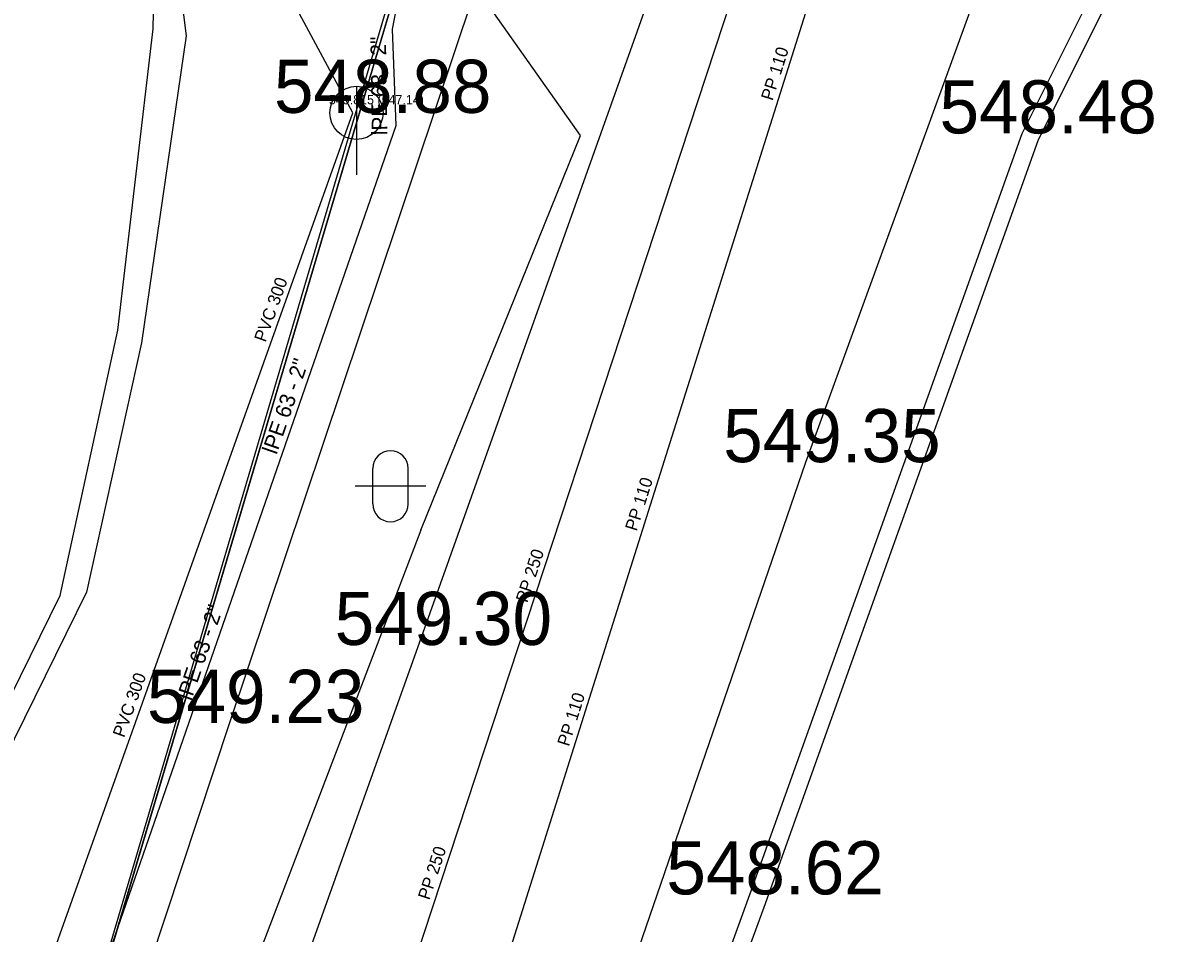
# Model space of a CAD drawing. Extents: x -669995 to -669686, y -1125551 to -1125263.
# Drawn here: x -669845.3 to -669829.31, y -1125387.03 to -1125374.18 of the extents above; entities that cross this region are included whole.
import ezdxf

# ---------------------------------------------------------------- set-up
doc = ezdxf.new("R2010")
doc.units = 0
for name, color, linetype in [('G_Bod_tecka', 7, 'Continuous'), ('G_Bod_vyska', 7, 'Continuous'), ('G_Plochy_zpevnene', 7, 'Continuous'), ('G_Ploty', 7, 'Continuous'), ('G_Site-kanalizace', 7, 'Continuous'), ('G_Z_ELsilove_nadz_kotovane', 7, 'Continuous'), ('G_Z_ELsilove_podz_kotovane', 7, 'Continuous'), ('G_Z_ELsilove_zrusene', 7, 'Continuous'), ('G_Z_KANAL_podz_kotovane', 7, 'Continuous'), ('G_Z_KANAL_podz_priblizne', 7, 'Continuous'), ('G_Z_PLYNY_podz_geodeticky', 7, 'Continuous'), ('G_Z_VODA_podz_kotovane', 7, 'Continuous'), ('G_Zelen-Znacky', 7, 'Continuous'), ('Vrstva 11', 7, 'Continuous'), ('Vrstva 17', 7, 'Continuous'), ('Vrstva 2', 7, 'Continuous'), ('Vrstva 21', 7, 'Continuous'), ('Vrstva 26', 7, 'Continuous'), ('Vrstva 3', 7, 'Continuous'), ('Vrstva 4', 7, 'Continuous'), ('Vrstva 5', 7, 'Continuous'), ('Vrstva 8', 7, 'Continuous')]:
    doc.layers.add(name, color=color, linetype=linetype)

msp = doc.modelspace()

# ---------------------------------------------------------------- linework, layer by layer
at = {"layer": 'G_Bod_tecka'}
for p, q in [((-669840.59, -1125375.45), (-669840.59, -1125375.45)), ((-669831.2, -1125375.74), (-669831.2, -1125375.74)), ((-669834.25, -1125380.38), (-669834.25, -1125380.38)), ((-669839.71, -1125382.96), (-669839.71, -1125382.96)), ((-669842.38, -1125384.06), (-669842.38, -1125384.06)), ((-669835.04, -1125386.48), (-669835.04, -1125386.48))]:
    msp.add_line(p, q, dxfattribs=at)
at = {"layer": 'G_Plochy_zpevnene'}
for p, q in [((-669834.97, -1125369.63), (-669839.7, -1125382.92)), ((-669834.25, -1125380.38), (-669831.09, -1125371.7)), ((-669838.26, -1125392.04), (-669834.25, -1125380.38)), ((-669839.7, -1125382.92), (-669842.04, -1125389.47))]:
    msp.add_line(p, q, dxfattribs=at)
at = {"layer": 'G_Ploty'}
for p, q in [((-669831.2, -1125375.74), (-669828.74, -1125370.82)), ((-669835.04, -1125386.48), (-669831.2, -1125375.74)), ((-669834.84, -1125386.66), (-669830.97, -1125375.84)), ((-669840.18, -1125400.57), (-669835.04, -1125386.48)), ((-669839.81, -1125400.29), (-669834.84, -1125386.66))]:
    msp.add_line(p, q, dxfattribs=at)
for points in [[(-669830.97, -1125375.84), (-669828.52, -1125370.93), (-669828.6, -1125370.86)], [(-669838.42, -1125372.24), (-669842.38, -1125384.06), (-669844.86, -1125391.55)]]:
    msp.add_lwpolyline(points, dxfattribs=at)
at = {"layer": 'G_Site-kanalizace'}
msp.add_line((-669840.59, -1125375.075), (-669840.59, -1125376.325), dxfattribs=at)
msp.add_circle((-669840.59, -1125375.45), 0.375, dxfattribs=at)
at = {"layer": 'G_Z_ELsilove_nadz_kotovane'}
msp.add_lwpolyline([(-669849.93, -1125407.07), (-669848.469, -1125402.12), (-669848.385, -1125401.833), (-669837.47, -1125364.84), (-669822.83, -1125326.67)], dxfattribs=at)
at = {"layer": 'G_Z_ELsilove_podz_kotovane'}
msp.add_lwpolyline([(-669793.678, -1125277.309), (-669806.73, -1125294.49), (-669822.69, -1125326.67), (-669837.43, -1125364.93), (-669849.93, -1125407.07), (-669860.28, -1125448.68)], dxfattribs=at)
at = {"layer": 'G_Z_ELsilove_zrusene'}
for points in [[(-669863.295, -1125360.816), (-669858.717, -1125362.962), (-669853.883, -1125366.153), (-669850.486, -1125367.71), (-669848.778, -1125369.103), (-669846.912, -1125369.899), (-669844.916, -1125370.944), (-669843.621, -1125372.127), (-669843.116, -1125373.389), (-669842.991, -1125374.364), (-669843.625, -1125378.696), (-669844.397, -1125382.214), (-669846.446, -1125386.365), (-669847.762, -1125391.264)], [(-669863.295, -1125360.816), (-669858.717, -1125362.962), (-669853.883, -1125366.153), (-669850.486, -1125367.71), (-669848.778, -1125369.103), (-669846.912, -1125369.899), (-669844.916, -1125370.944), (-669843.621, -1125372.127), (-669843.116, -1125373.389), (-669842.991, -1125374.364), (-669843.625, -1125378.696), (-669844.397, -1125382.214), (-669846.446, -1125386.365), (-669847.762, -1125391.264)], [(-669848.073, -1125391.245), (-669846.736, -1125386.251), (-669844.771, -1125382.262), (-669843.956, -1125378.516), (-669843.46, -1125374.264), (-669843.446, -1125373.566), (-669844.054, -1125372.192), (-669845.04, -1125371.262), (-669847.052, -1125370.29), (-669848.855, -1125369.426), (-669850.664, -1125368.068), (-669854.033, -1125366.453), (-669859.083, -1125363.428), (-669863.5, -1125361.121)], [(-669848.073, -1125391.245), (-669846.736, -1125386.251), (-669844.771, -1125382.262), (-669843.956, -1125378.516), (-669843.46, -1125374.264), (-669843.446, -1125373.566), (-669844.054, -1125372.192), (-669845.04, -1125371.262), (-669847.052, -1125370.29), (-669848.855, -1125369.426), (-669850.664, -1125368.068), (-669854.033, -1125366.453), (-669859.083, -1125363.428), (-669863.5, -1125361.121)]]:
    msp.add_lwpolyline(points, dxfattribs=at)
at = {"layer": 'G_Z_KANAL_podz_kotovane'}
msp.add_line((-669834.34, -1125370.92), (-669844.67, -1125402.32), dxfattribs=at)
msp.add_lwpolyline([(-669837.47, -1125406.42), (-669844.1, -1125405.26), (-669833.36, -1125371.21), (-669821.31, -1125332.23), (-669811.44, -1125307.86), (-669795.39, -1125283.71), (-669791, -1125278.72), (-669790.199, -1125277.833)], dxfattribs=at)
at = {"layer": 'G_Z_KANAL_podz_priblizne'}
msp.add_lwpolyline([(-669859.5, -1125451.55), (-669856.48, -1125430.45), (-669853.73, -1125415.63), (-669852.14, -1125407.38), (-669851.85, -1125406.81), (-669846.78, -1125392.66), (-669840.64, -1125375.45), (-669843.45, -1125370.23)], dxfattribs=at)
at = {"layer": 'G_Z_PLYNY_podz_geodeticky'}
for points in [[(-669839.68, -1125381.34), (-669837.43, -1125375.77), (-669838.71, -1125373.96)], [(-669839.68, -1125381.34), (-669843.56, -1125391.5), (-669845.77, -1125398.22), (-669846.85, -1125401.64), (-669847.2, -1125402.75), (-669848.28, -1125405.76), (-669848.45, -1125406.31), (-669848.51, -1125406.54), (-669849.81, -1125412.17), (-669852.19, -1125424.43), (-669853.31, -1125431.05), (-669856.64, -1125450), (-669860.14, -1125455.63), (-669860.74, -1125456.58)]]:
    msp.add_lwpolyline(points, dxfattribs=at)
at = {"layer": 'G_Z_VODA_podz_kotovane'}
msp.add_lwpolyline([(-669858.63, -1125450.57), (-669858.25, -1125448.42), (-669857.85, -1125445.05), (-669856.38, -1125434.43), (-669854.37, -1125424.91), (-669851.09, -1125407.69), (-669849.25, -1125402.21), (-669840.03, -1125375.63), (-669840.08, -1125374.27), (-669839.76, -1125372.61), (-669839.5, -1125370.59), (-669837.98, -1125365.03), (-669838.35, -1125363.15), (-669838.04, -1125362.68), (-669836.94, -1125362.97)], dxfattribs=at)
at = {"layer": 'G_Zelen-Znacky'}
for p, q in [((-669840.36, -1125380.97), (-669840.36, -1125380.47)), ((-669839.86, -1125380.97), (-669839.86, -1125380.47)), ((-669839.61, -1125380.72), (-669840.61, -1125380.72))]:
    msp.add_line(p, q, dxfattribs=at)
for centre, start, end in [((-669840.11, -1125380.47), 0, 180), ((-669840.11, -1125380.97), 180, 0)]:
    msp.add_arc(centre, 0.25, start, end, dxfattribs=at)
at = {"layer": 'Vrstva 11'}
msp.add_line((-669834.34, -1125370.92), (-669844.67, -1125402.32), dxfattribs=at)
at = {"layer": 'Vrstva 17'}
msp.add_lwpolyline([(-669859.5, -1125451.55), (-669856.48, -1125430.45), (-669853.73, -1125415.63), (-669852.14, -1125407.38), (-669851.85, -1125406.81), (-669846.78, -1125392.66), (-669840.64, -1125375.45), (-669843.45, -1125370.23)], dxfattribs=at)
at = {"layer": 'Vrstva 21'}
msp.add_lwpolyline([(-669837.47, -1125406.42), (-669844.1, -1125405.26), (-669833.36, -1125371.21), (-669821.31, -1125332.23), (-669811.44, -1125307.86), (-669795.39, -1125283.71), (-669791, -1125278.72), (-669790.199, -1125277.833)], dxfattribs=at)
at = {"layer": 'Vrstva 26'}
msp.add_lwpolyline([(-669858.63, -1125450.57), (-669858.245, -1125448.421), (-669857.85, -1125445.05), (-669856.38, -1125434.43), (-669854.37, -1125424.91), (-669851.09, -1125407.69), (-669849.25, -1125402.21), (-669840.03, -1125375.63), (-669840.08, -1125374.27), (-669839.76, -1125372.61), (-669839.5, -1125370.59), (-669837.98, -1125365.03), (-669838.35, -1125363.15), (-669838.04, -1125362.68), (-669836.94, -1125362.97)], dxfattribs=at)
at = {"layer": 'Vrstva 5'}
msp.add_line((-669837.43, -1125364.93), (-669849.93, -1125407.07), dxfattribs=at)
at = {"layer": 'Vrstva 8'}
msp.add_line((-669840.64, -1125375.45), (-669840.64, -1125375.45), dxfattribs=at)

# ---------------------------------------------------------------- texts
at = {"layer": 'G_Bod_vyska'}
for s, p in [('548.88', (-669841.754, -1125375.45)), ('548.48', (-669832.364, -1125375.74)), ('549.35', (-669835.416, -1125380.38)), ('549.30', (-669840.898, -1125382.96)), ('549.23', (-669843.546, -1125384.06)), ('548.62', (-669836.218, -1125386.48))]:
    msp.add_text(s, height=0.75, dxfattribs=at).set_placement(p)
at = {"layer": 'Vrstva 2'}
msp.add_text('549.815 (547.14)', height=0.13163, dxfattribs=at).set_placement((-669840.979, -1125375.329))
at = {"layer": 'Vrstva 3'}
for s, rotation, p in [('PP 110', 72.491, (-669834.72, -1125375.288)), ('PVC 300', 70.3279, (-669841.874, -1125378.696)), ('PP 110', 72.5034, (-669836.637, -1125381.363)), ('PP 250', 71.7606, (-669838.181, -1125382.374)), ('PVC 300', 70.3485, (-669843.869, -1125384.277)), ('PP 110', 72.5034, (-669837.594, -1125384.401)), ('PP 250', 71.8126, (-669839.561, -1125386.569))]:
    msp.add_text(s, height=0.1755, rotation=rotation, dxfattribs=at).set_placement(p)
at = {"layer": 'Vrstva 4'}
for rotation, p in [(90.8814, (-669840.153, -1125375.763)), (70.8776, (-669841.718, -1125380.282)), (70.8776, (-669842.923, -1125383.757))]:
    msp.add_text('lPE 63 - 2"', height=0.21938, rotation=rotation, dxfattribs=at).set_placement(p)

doc.saveas('drawing.dxf')
